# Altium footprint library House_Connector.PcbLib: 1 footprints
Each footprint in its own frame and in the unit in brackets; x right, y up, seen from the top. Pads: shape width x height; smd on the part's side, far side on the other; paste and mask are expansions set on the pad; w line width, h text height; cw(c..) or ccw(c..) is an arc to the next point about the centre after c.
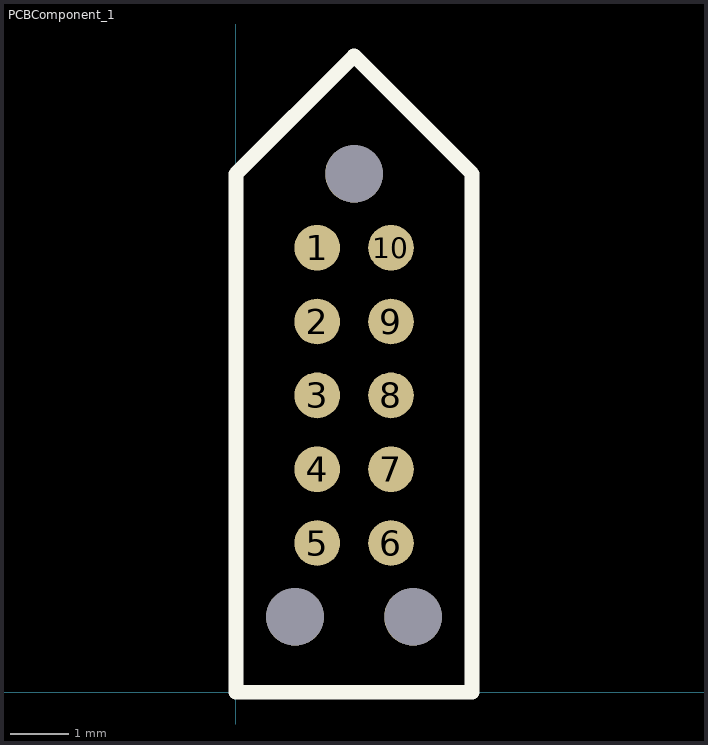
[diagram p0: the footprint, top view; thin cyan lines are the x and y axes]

## PCBComponent_1 [mil]
pads (13):
  round 30.98 smd paste+0 mask+1.5: 1(55.04,301) 2(55.04,251) 3(55.04,201) 4(55.04,151) 5(55.04,101) 6(105.04,101) 7(105.04,151) 8(105.04,201) 9(105.04,251) 10(105.04,301)
  round 39.02 hole 39.02 unplated mask+1.5: ""(40.08,51) ""(80.04,351) ""(120,51)
Top Overlay:
  lines w10: 0,350.92 0,0 160,0 160,351 80.04,430.96 0.08,351
M5 Assembly Top:
  text ".Designator" at 218,-9 h40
